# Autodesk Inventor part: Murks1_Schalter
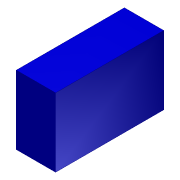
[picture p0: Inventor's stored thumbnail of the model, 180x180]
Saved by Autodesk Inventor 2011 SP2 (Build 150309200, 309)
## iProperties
Created: 2012-07
Part Number: Murks1_Schalter
Document SubType Name: Modeling
Designer: Thomas Kötschau
Density: 1 g/cm^3
Author: Thomas Kötschau
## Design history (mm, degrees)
sketch "Skizze1"
  geometry: L1 (-10, 27.5)-(10, 27.5); L2 (10, 27.5)-(10, -27.5); L3 (10, -27.5)-(-10, -27.5); L4 (-10, -27.5)-(-10, 27.5); L5 (-10, 27.5)-(10, -27.5); 2 further points
  constraints: 10 end point, 2 parallel, 1 coincident, 1 horizontal, 1 midpoint, 1 perpendicular
  dimensions: "d0" = 20 distance of L1.start L1.end; "d1" = 55 distance of L1.end L2.end
extrude "Extrusion1" new body sketch "Skizze1" distance "d2" = 35; taper "d3" = 0 deg
node "Volumenkörper1"
